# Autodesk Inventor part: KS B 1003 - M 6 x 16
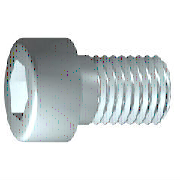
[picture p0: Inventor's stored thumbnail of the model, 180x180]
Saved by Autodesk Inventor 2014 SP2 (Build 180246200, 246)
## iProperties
Created: 2009-02
Part Number: KS B 1003 - M 6 x 16
Material: Steel, Mild
Description: 6각머리 태핑 나사
Document SubType Name: Modeling
Standard: KS B 1003
Designer: KYOUNG IL JANG
Standards Organization: KS
Language: ko-KR
Size Designation: M 6 x 16
Categories: <MemberInstance><Categories><Category DisplayName="조임쇠" InternalName="e4da775c-781d-43d5-af7c-5136215cf5a6" Mnemonic="FSTN"><Category DisplayName="볼트" InternalN
Density: 1 g/cm^3
Appearance: Metal-Steel
Company: 한국ATC센터
IsCustomPart: 0
Author: KYOUNG IL JANG
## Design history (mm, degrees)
sketch "스케치1"
  geometry: L1 (-1.333, 0)-(16, 0); L2 (16, 0)-(16, 3); L3 (16, 3)-(2.5, 3); L4 (2.5, 3)-(1.886, 3); L5 (1.886, 3)-(0, 3); L6 (0, 3)-(0, 5); L7 (0, 5)-(-6, 5); L8 (-6, 5)-(-6, 2.887); L9 (-6, 2.887)-(-3, 2.887); L10 (-3, 2.887)-(-1.333, 0); L11 (-10.4, 0)-(20.4, 0) reference; L12 (0, -1)-(0, 6) reference; L13 (2.5, 3)-(0, 3)
  constraints: 22 end point, 6 parallel, 2 collinear, 2 perpendicular, 1 horizontal, 1 point on line
  dimensions: "d1" = 13.5 distance from line of L3.end L2 (= GEL); "d2" = 0.61355 distance of L4.end L3.end (computed from GAL); "d3" = 6 distance between parallel lines of L8 L6 (= KOH); "d4" = 3 distance of L8.end L9.end (= INTI); "d5" = 60 deg angle of L10 L1; "d6" = 6 diameter of L3 L1 (= GD); "d7" = 6 diameter of L5 L1 (= BDM); "d8" = 5.7735 diameter of L9 L1 (= 1.1547 x SW); "d9" = 10 diameter of L7 L1 (= KOD); "d26" = 16 distance between parallel lines of L12 L2 (= NLG)
revolve "본체" sketch "스케치1" stored, may be unused: angle "d10" = 90 deg
sketch "스케치2"
  geometry: L1 (0, -7)-(0, 7) reference; L2 (-7, 0)-(7, 0) reference; L3 (2.887, 0)-(1.443, -2.5); L4 (1.443, -2.5)-(-1.443, -2.5); L5 (-1.443, -2.5)-(-2.887, 0); L6 (-2.887, 0)-(-1.443, 2.5); L7 (-1.443, 2.5)-(1.443, 2.5); L8 (1.443, 2.5)-(2.887, 0); 2 further points
  constraints: 12 end point, 1 coincident, 1 horizontal alignment, 1 point on line, 12 other
extrude "슬롯" join sketch "스케치2" stored distance "d11" = 10; taper "d12" = 0 deg
workplane "Work Plane1"
fillet "Fillet2" dims "d30" = 0.1 (= R)
body "Solid1"
fillet "모깎기1" dims "d17" = 0.6 (= RR)
feature "스레드" dims "d13" = 13.5 (= GEL), "d14" = 0
chamfer "모따기1" distance "d15" = 0.61345 (= -0.5 x SPD + 0.5 x GD); stored, may be unused: second distance "d16" = 0.61345 (= GUL), angle "d27" = 45 deg
other parameters: "GD" = 6 (= NND) [user parameter; used in 2 equation terms], "NLG" = 16 [user parameter; used in 1 equation term], "GEL" = 13.5 [user parameter; used in 2 equation terms], "KOD" = 10 [user parameter; used in 1 equation term], "KOH" = 6 [user parameter; used in 1 equation term], "INTI" = 3 [user parameter; used in 1 equation term], "GAL" = 0.61345 (= 0.61345 x PTC) [user parameter; used in 1 equation term], "GUL" = 0.61345 (= 0.61345 x PTC) [user parameter; used in 1 equation term], "BDM" = 6 (= NND) [user parameter; used in 1 equation term], "SW" = 5 [user parameter; used in 2 equation terms], "RR" = 0.6 [user parameter; used in 1 equation term], "SPD" = 4.7731 (= NND - 1.2269 x PTC) [user parameter; used in 1 equation term], "d19" = 0, "d28" = 0, "d29" = 0, "R" = 0.1 [user parameter; used in 1 equation term], "PHH" = 0.25 [user parameter], "GD1" = 4.7731 (= THREADDIA - 1.2269 x PTC) [user parameter], "THREADDIA" = 6 [user parameter; used in 1 equation term], "FAWI" = 45 deg [user parameter], "PTC" = 1 [user parameter; used in 5 equation terms], "NND" = 6 [user parameter; used in 3 equation terms], "TOA" = 30 deg [user parameter], "E0" = 5.775 (= 1.155 x SW) [user parameter]
